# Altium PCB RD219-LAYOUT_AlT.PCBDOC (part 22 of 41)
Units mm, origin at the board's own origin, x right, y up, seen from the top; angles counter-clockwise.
Board outline 209.75 x 159.97 mm, 2 copper layers (TOP, BOTTOM), stack 0 mm thick; 398 components, 199 nets, 1469 pads, 0 vias.
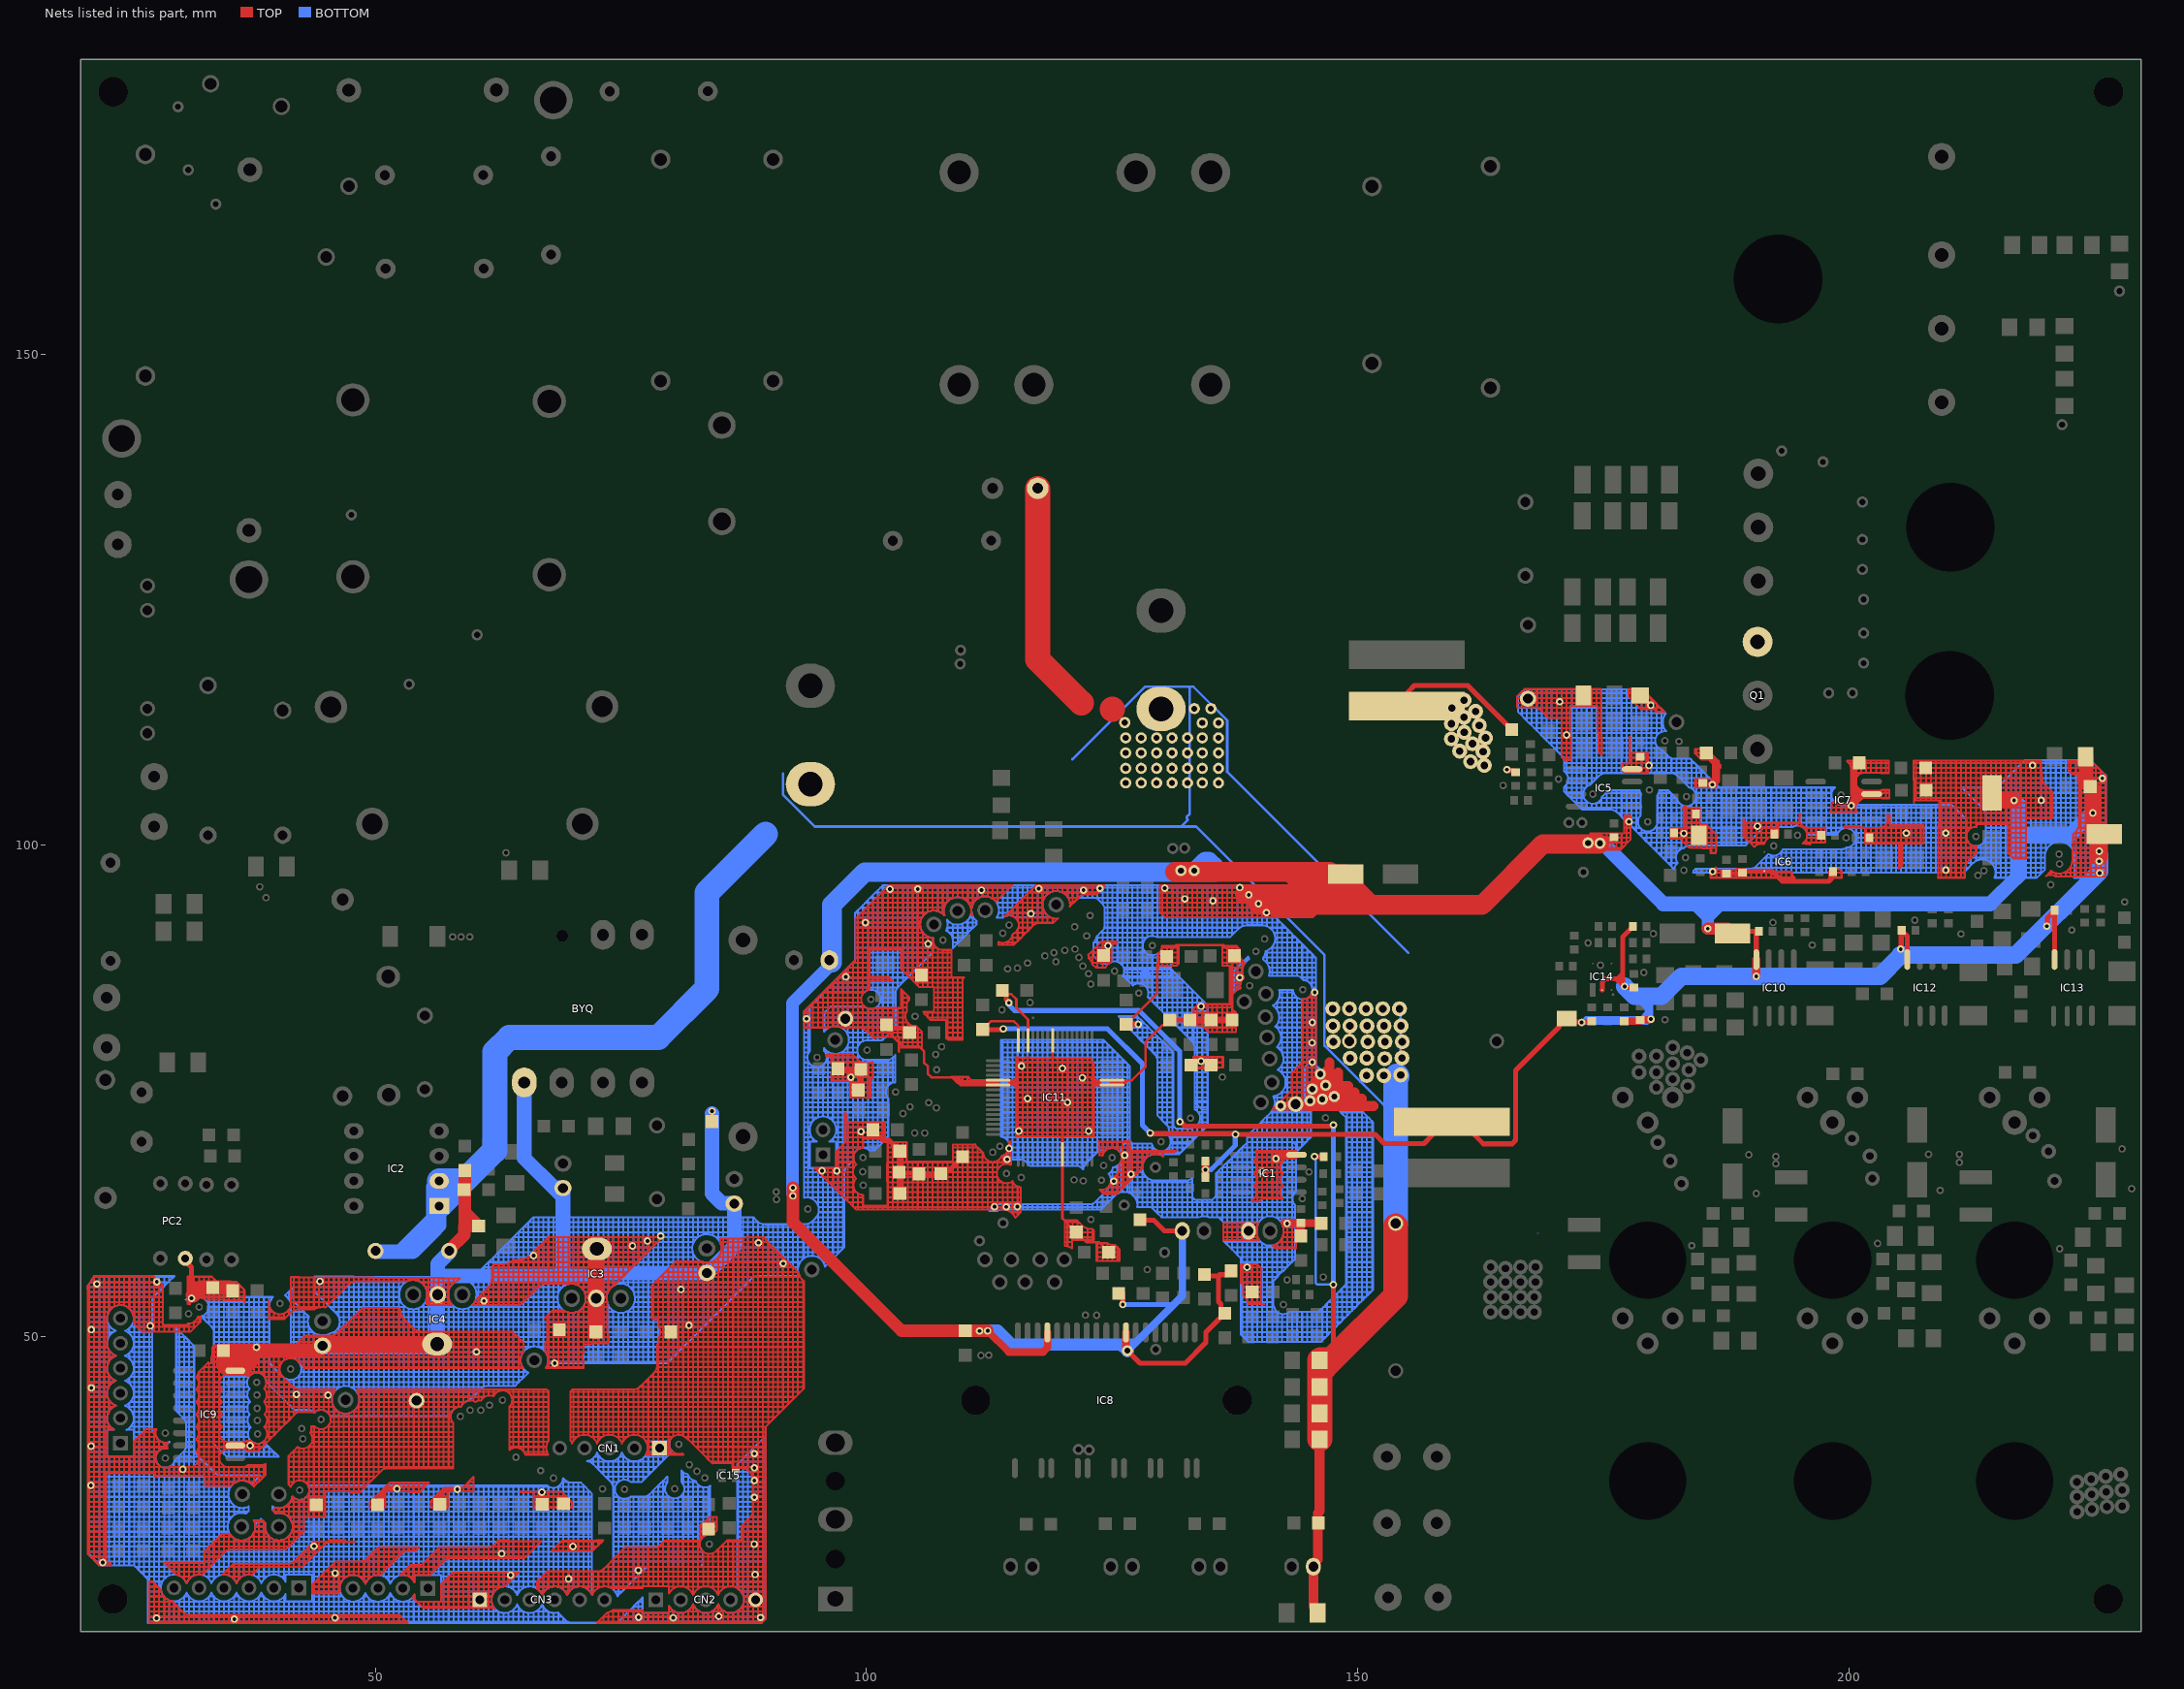
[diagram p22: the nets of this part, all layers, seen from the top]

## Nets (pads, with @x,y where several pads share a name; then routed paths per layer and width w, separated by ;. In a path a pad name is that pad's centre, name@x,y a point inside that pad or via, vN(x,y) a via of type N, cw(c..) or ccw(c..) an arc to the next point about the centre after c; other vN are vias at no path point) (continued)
GND: (continued)
  BOTTOM w0.203: 36.129,41.844 36.129,42.352 ; 36.129,41.844 36.637,41.844 ; 36.129,42.352 36.129,42.86 ; 36.129,42.352 36.637,42.352 ; 36.129,42.86 36.129,43.368 ; 36.129,42.86 36.637,42.86 ; 36.129,43.368 36.129,43.876 ; 36.129,43.368 36.637,43.368 ; 36.129,43.876 36.129,44.384 ; 36.129,43.876 36.637,43.876 ; 36.129,44.384 36.129,44.892 ; 36.129,44.384 36.637,44.384 ; 36.129,44.892 36.129,45.4 ; 36.129,44.892 36.637,44.892 ; 36.129,45.4 36.129,45.908 ; 36.129,45.4 36.637,45.4 ; 36.129,45.908 36.129,46.416 ; 36.129,45.908 36.637,45.908 ; 36.129,46.416 36.129,46.924 ; 36.129,46.416 36.637,46.416 ; 36.129,46.924 36.129,47.432 ; 36.129,46.924 36.637,46.924 ; 36.129,47.432 36.129,47.94 ; 36.129,47.432 36.637,47.432 ; 36.129,47.94 36.129,48.448 ; 36.129,47.94 36.637,47.94 ; 36.129,48.448 36.129,48.956 ; 36.129,48.448 36.637,48.448 ; 36.129,48.956 36.129,49.464 ; 36.129,48.956 36.637,48.956 ; 36.129,49.464 36.129,49.972 ; 36.129,49.464 36.637,49.464 ; 36.129,49.972 36.129,50.48 ; 36.129,49.972 36.637,49.972 ; 36.129,50.48 36.129,50.988 ; 36.129,50.48 36.637,50.48 ; 36.129,50.988 36.129,51.496 ; 36.129,50.988 36.637,50.988 ; 36.129,51.496 36.129,52.004 ; 36.129,51.496 36.637,51.496 ; 36.129,52.004 36.129,52.512 ; 36.129,52.004 36.637,52.004 ; 36.129,52.512 36.129,53.02 ; 36.129,52.512 36.637,52.512 ; 36.129,53.02 36.129,53.528 ; 36.129,53.02 36.637,53.02 ; 36.129,53.528 36.129,54.036 ; 36.129,53.528 36.637,53.528 ; 36.129,54.036 36.129,54.073 ; 36.129,54.036 36.637,54.036 ; 36.129,54.073 36.637,54.073 ; 36.424,25.588 cw(c37.145,24.445) 36.429,25.591 cw(c37.145,24.445) 36.637,25.697 ; 36.637,20.889 36.637,21.016 ; 36.637,20.889 37.145,20.889 ; 36.637,21.016 36.637,21.524 ; 36.637,21.016 37.145,21.016 ; 36.637,21.524 36.637,22.032 ; 36.637,21.524 37.145,21.524 ; 36.637,22.032 36.637,22.54 ; 36.637,22.032 37.145,22.032 ; 36.637,22.54 36.637,23.048 ; 36.637,22.54 37.145,22.54 ; 36.637,23.048 37.145,23.048 ; 36.637,23.048 36.637,23.193 ; 36.637,23.193 ccw(c37.145,24.445) 36.639,23.192 ccw(c37.145,24.445) 37.145,23.093 ; 36.637,25.697 cw(c37.145,24.445) 36.639,25.698 cw(c37.145,24.445) 37.145,25.797 ; 36.637,25.698 36.637,26.096 ; 36.637,26.096 36.637,26.604 ; 36.637,26.096 37.145,26.096 ; 36.637,26.604 36.637,27.112 ; 36.637,26.604 37.145,26.604 ; 36.637,27.112 36.637,27.62 ; 36.637,27.112 37.145,27.112 ; 36.637,27.62 36.637,28.128 ; 36.637,27.62 37.145,27.62 ; 36.637,28.128 36.637,28.636 ; 36.637,28.128 37.145,28.128 ; 36.637,28.636 36.637,29.144 ; 36.637,28.636 37.145,28.636 ; 36.637,29.144 37.145,29.144 ; 36.637,29.144 36.637,29.29 ; 36.637,29.29 ccw(c36.383,30.668) 36.793,29.328 ccw(c36.383,30.668) 37.145,29.492 ; 36.637,32.046 36.637,32.192 ; 36.637,32.192 37.044,32.192 ; 36.637,32.192 36.637,32.579 ; 36.637,32.579 ccw(c36.463,33.97) 37.115,32.729 ; 36.637,35.361 cw(c36.463,33.97) 37.056,35.24 ; 36.637,35.361 36.637,35.748 ; 36.637,35.748 36.637,35.908 ; 36.637,35.748 37.145,35.748 ; 36.637,35.908 37.145,35.908 ; 36.637,37.79 36.637,38.288 ; 36.637,37.79 37.145,37.79 ; 36.637,38.288 36.637,38.796 ; 36.637,38.288 37.145,38.288 ; 36.637,38.796 36.637,39.304 ; 36.637,38.796 pad.@37.145,38.796 ; 36.637,39.304 36.637,39.812 ; 36.637,39.304 37.145,39.304 ; 36.637,39.812 36.637,40.32 ; 36.637,39.812 37.087,39.812 ; 36.637,40.32 36.637,40.828 ; 36.637,40.32 37.064,40.32 ; 36.637,40.828 37.145,40.828 ; 36.637,40.828 36.637,41.336 ; 36.637,41.336 36.637,41.844 ; 36.637,41.844 36.637,42.352 ; 36.637,41.844 37.081,41.844 ; 36.637,42.352 36.637,42.86 ; 36.637,42.352 37.059,42.352 ; 36.637,42.86 36.637,43.368 ; 36.637,42.86 37.002,42.86 ; 36.637,43.368 37.145,43.368 ; 36.637,43.368 36.637,43.876 ; 36.637,43.876 36.637,44.384 ; 36.637,43.876 37.005,43.876 ; 36.637,44.384 36.637,44.892 ; 36.637,44.384 37.034,44.384 ; 36.637,44.892 36.637,45.4 ; 36.637,44.892 37.066,44.892 ; 36.637,45.4 36.637,45.908 ; 36.637,45.4 36.948,45.4 ; 36.637,45.908 36.637,46.416 ; 36.637,45.908 37.115,45.908 ; 36.637,46.416 36.637,46.924 ; 36.637,46.416 37.145,46.416 ; 36.637,46.924 36.637,47.432 ; 36.637,46.924 37.145,46.924 ; 36.637,47.432 36.637,47.94 ; 36.637,47.432 37.145,47.432 ; 36.637,47.94 36.637,48.448 ; 36.637,47.94 37.145,47.94 ; 36.637,48.448 36.637,48.956 ; 36.637,48.448 37.145,48.448 ; 36.637,48.956 36.637,49.464 ; 36.637,48.956 37.145,48.956 ; 36.637,49.464 36.637,49.972 ; 36.637,49.464 37.145,49.464 ; 36.637,49.972 36.637,50.48 ; 36.637,49.972 37.145,49.972 ; 36.637,50.48 36.637,50.988 ; 36.637,50.48 37.145,50.48 ; 36.637,50.988 36.637,51.496 ; 36.637,50.988 37.145,50.988 ; 36.637,51.496 36.637,52.004 ; 36.637,51.496 37.145,51.496 ; 36.637,52.004 36.637,52.512 ; 36.637,52.004 37.145,52.004 ; 36.637,52.512 36.637,53.02 ; 36.637,52.512 37.145,52.512 ; 36.637,53.02 36.637,53.528 ; 36.637,53.02 37.145,53.02 ; 36.637,53.528 36.637,54.036 ; 36.637,53.528 37.145,53.528 ; 36.637,54.036 36.637,54.073 ; 36.637,54.036 37.145,54.036 ; 36.637,54.073 37.145,54.073 ; 36.948,45.4 ccw(c37.93,45.359) 36.948,45.394 ccw(c37.93,45.359) 37.066,44.892 ; 36.948,45.4 cw(c37.93,45.359) 37.115,45.908 ; 37.002,42.86 ccw(c37.973,42.712) 37.059,42.352 ; 37.002,42.86 cw(c37.973,42.712) 37.003,42.866 cw(c37.973,42.712) 37.145,43.241 ; 37.005,43.876 ccw(c37.967,44.076) 37.006,43.872 ccw(c37.967,44.076) 37.145,43.537 ; 37.005,43.876 cw(c37.967,44.076) 37.032,44.379 cw(c37.967,44.076) 37.034,44.384 ; 37.034,44.384 cw(c37.967,44.076) 37.145,44.615 ; 37.044,32.192 37.115,32.263 37.115,32.729 ; 37.056,35.24 cw(c36.463,33.97) 37.143,35.196 cw(c36.463,33.97) 37.145,35.194 ; 37.056,35.24 37.145,35.24 ; 37.059,42.352 ccw(c37.973,42.712) 37.145,42.183 ; 37.064,40.32 ccw(c38.024,40.11) 37.062,40.314 ccw(c38.024,40.11) 37.087,39.812 ; 37.064,40.32 cw(c38.024,40.11) 37.145,40.55 ; 37.066,44.892 ccw(c37.93,45.359) 37.145,44.769 ; 37.081,41.844 cw(c37.995,41.485) 37.145,41.978 ; 37.087,39.812 ccw(c38.024,40.11) 37.145,39.67 ; 37.115,45.908 cw(c37.93,45.359) 37.145,45.95 37.145,46.416 ; 37.145,20.889 37.145,21.016 ; 37.145,20.889 37.653,20.889 ; 37.145,21.016 37.145,21.524 ; 37.145,21.016 37.653,21.016 ; 37.145,21.524 37.145,22.032 ; 37.145,21.524 37.653,21.524 ; 37.145,22.032 37.145,22.54 ; 37.145,22.032 37.653,22.032 ; 37.145,22.54 37.145,23.048 ; 37.145,22.54 37.653,22.54 ; 37.145,23.048 37.653,23.048 ; 37.145,23.048 37.145,23.093 ; 37.145,23.093 ccw(c37.145,24.445) 37.651,23.192 ccw(c37.145,24.445) 37.653,23.192 ; 37.145,25.797 cw(c37.145,24.445) 37.651,25.698 cw(c37.145,24.445) 37.653,25.698 ; 37.145,25.797 37.145,26.096 ; 37.145,26.096 37.145,26.604 ; 37.145,26.096 37.653,26.096 ; 37.145,26.604 37.145,27.112 ; 37.145,26.604 37.653,26.604 ; 37.145,27.112 37.145,27.62 ; 37.145,27.112 37.653,27.112 ; 37.145,27.62 37.145,28.128 ; 37.145,27.62 37.653,27.62 ; 37.145,28.128 37.145,28.636 ; 37.145,28.128 37.653,28.128 ; 37.145,28.636 37.145,29.144 ; 37.145,28.636 37.653,28.636 ; 37.145,29.144 37.653,29.144 ; 37.145,29.144 37.145,29.492 ; 37.145,29.492 ccw(c36.383,30.668) 37.146,29.493 ccw(c36.383,30.668) 37.349,29.652 ; 37.145,35.194 37.145,35.24 ; 37.145,35.24 37.145,35.748 ; 37.145,35.24 37.639,35.24 ; 37.145,35.748 37.145,35.908 ; 37.145,35.748 37.653,35.748 ; 37.145,35.908 37.653,35.908 ; 37.145,37.79 37.145,38.288 ; 37.145,37.79 37.653,37.79 ; 37.145,38.288 pad.@37.145,38.796 ; 37.145,38.288 37.653,38.288 ; pad.@37.145,38.796 37.653,38.796 ; pad.@37.145,38.796 37.145,39.304 ; 37.145,39.304 37.461,39.304 ; 37.145,39.304 37.145,39.67 ; 37.145,39.67 ccw(c38.024,40.11) 37.148,39.664 ccw(c38.024,40.11) 37.46,39.305 ccw(c38.024,40.11) 37.461,39.304 ; 37.145,40.55 37.145,40.828 ; 37.145,40.828 37.145,40.992 ; 37.145,40.828 37.264,40.828 ; 37.145,40.992 ccw(c37.995,41.485) 37.264,40.828 ; 37.145,41.978 37.145,42.183 ; 37.145,43.241 cw(c37.973,42.712) 37.241,43.368 ; 37.145,43.241 37.145,43.368 ; 37.145,43.368 37.241,43.368 ; 37.145,43.368 37.145,43.537 ; 37.145,44.615 37.145,44.769 ; 37.145,46.416 37.145,46.924 ; 37.145,46.416 37.653,46.416 ; 37.145,46.924 37.145,47.432 ; 37.145,46.924 37.653,46.924 ; 37.145,47.432 37.145,47.94 ; 37.145,47.432 37.653,47.432 ; 37.145,47.94 37.145,48.448 ; 37.145,47.94 37.653,47.94 ; 37.145,48.448 37.145,48.956 ; 37.145,48.448 37.653,48.448 ; 37.145,48.956 37.145,49.464 ; 37.145,48.956 pad.@37.653,48.956 ; 37.145,49.464 37.145,49.972 ; 37.145,49.464 37.653,49.464 ; 37.145,49.972 37.145,50.48 ; 37.145,49.972 37.653,49.972 ; 37.145,50.48 37.145,50.988 ; 37.145,50.48 37.653,50.48 ; 37.145,50.988 37.145,51.496 ; 37.145,50.988 37.653,50.988 ; 37.145,51.496 37.145,52.004 ; 37.145,51.496 37.653,51.496 ; 37.145,52.004 37.145,52.512 ; 37.145,52.004 37.653,52.004 ; 37.145,52.512 37.145,53.02 ; 37.145,52.512 37.653,52.512 ; 37.145,53.02 37.145,53.528 ; 37.145,53.02 37.653,53.02 ; 37.145,53.528 37.145,54.036 ; 37.145,53.528 37.653,53.528 ; 37.145,54.036 37.145,54.073 ; 37.145,54.036 37.653,54.036 ; 37.145,54.073 37.653,54.073 ; 37.349,29.652 ccw(c36.383,30.668) 37.357,29.66 ccw(c36.383,30.668) 37.653,30.075 37.653,29.652 ; 37.349,29.652 37.653,29.652 ; 37.461,39.304 ccw(c38.024,40.11) 37.653,39.2 ; 37.639,35.24 37.653,35.254 ; 37.653,20.889 37.653,21.016 ; 37.653,20.889 38.161,20.889 ; 37.653,21.016 37.653,21.524 ; 37.653,21.016 38.161,21.016 ; 37.653,21.524 37.653,22.032 ; 37.653,21.524 38.161,21.524 ; 37.653,22.032 37.653,22.54 ; 37.653,22.032 38.161,22.032 ; 37.653,22.54 37.653,23.048 ; 37.653,22.54 38.161,22.54 ; 37.653,23.048 38.161,23.048 ; 37.653,23.048 37.653,23.192 ; 37.653,23.192 ccw(c37.145,24.445) 38.161,23.554 ; 37.653,25.698 37.653,26.096 ; 37.653,26.096 37.653,26.604 ; 37.653,26.096 38.161,26.096 ; 37.653,26.604 37.653,27.112 ; 37.653,26.604 38.161,26.604 ; 37.653,27.112 37.653,27.62 ; 37.653,27.112 38.161,27.112 ; 37.653,27.62 37.653,28.128 ; 37.653,27.62 38.161,27.62 ; 37.653,28.128 37.653,28.636 ; 37.653,28.128 38.161,28.128 ; 37.653,28.636 37.653,29.144 ; 37.653,28.636 38.161,28.636 ; 37.653,29.144 37.653,29.652 ; 37.653,29.144 38.161,29.144 ; 37.653,29.652 38.161,29.652 ; 37.653,35.254 38.161,35.762 ; 37.653,35.254 37.653,35.748 ; 37.653,35.748 37.653,35.908 ; 37.653,35.908 38.161,35.908 ; 37.653,37.79 37.653,38.288 ; 37.653,37.79 38.161,37.79 ; 37.653,38.288 37.653,38.796 ; 37.653,38.288 38.161,38.288 ; 37.653,38.796 38.161,38.796 ; 37.653,38.796 37.653,39.2 ; 37.653,46.302 cw(c37.93,45.359) 37.659,46.304 cw(c37.93,45.359) 37.93,46.342 cw(c37.93,45.359) 38.161,46.314 ; 37.653,46.302 37.653,46.416 ; 37.653,46.416 37.653,46.924 ; 37.653,46.416 38.161,46.416 ; 37.653,46.924 37.653,47.432 ; 37.653,46.924 38.161,46.924 ; 37.653,47.432 37.653,47.94 ; 37.653,47.432 38.161,47.432 ; 37.653,47.94 37.653,48.448 ; 37.653,47.94 38.161,47.94 ; 37.653,48.448 38.161,48.448 ; 37.653,48.448 pad.@37.653,48.956 ; pad.@37.653,48.956 37.653,49.464 ; pad.@37.653,48.956 pad.@38.161,48.956 ; 37.653,49.464 37.653,49.972 ; 37.653,49.464 38.161,49.464 ; 37.653,49.972 37.653,50.48 ; 37.653,49.972 38.161,49.972 ; 37.653,50.48 37.653,50.988 ; 37.653,50.48 38.161,50.48 ; 37.653,50.988 37.653,51.496 ; 37.653,50.988 38.161,50.988 ; 37.653,51.496 37.653,52.004 ; 37.653,51.496 38.161,51.496 ; 37.653,52.004 37.653,52.512 ; 37.653,52.004 38.161,52.004 ; 37.653,52.512 37.653,53.02 ; 37.653,52.512 38.161,52.512 ; 37.653,53.02 37.653,53.528 ; 37.653,53.02 38.161,53.02 ; 37.653,53.528 37.653,54.036 ; 37.653,53.528 38.161,53.528 ; 37.653,54.036 37.653,54.073 ; 37.653,54.036 38.161,54.036 ; 37.653,54.073 38.161,54.073 ; 37.689,30.16 ccw(c36.383,30.668) 37.785,30.668 ; 37.689,30.16 38.161,30.16 ; 37.772,30.859 cw(c36.383,30.668) 37.785,30.668 ; 37.772,30.859 38.088,31.176 ; 37.785,30.668 38.161,30.668 ; 38.088,31.176 38.161,31.176 ; 38.088,31.176 38.161,31.249 ; 38.161,20.889 38.161,21.016 ; 38.161,20.889 38.669,20.889 ; 38.161,21.016 38.161,21.524 ; 38.161,21.016 38.669,21.016 ; 38.161,21.524 38.161,22.032 ; 38.161,21.524 38.669,21.524 ; 38.161,22.032 38.161,22.54 ; 38.161,22.032 38.669,22.032 ; 38.161,22.54 38.161,23.048 ; 38.161,22.54 38.669,22.54 ; 38.161,23.048 38.669,23.048 ; 38.161,23.048 38.161,23.554 ; 38.161,23.554 ccw(c37.145,24.445) 38.163,23.556 ; 38.161,25.336 cw(c37.145,24.445) 38.165,25.332 cw(c37.145,24.445) 38.338,25.08 ; 38.161,25.336 38.161,25.588 ; 38.161,25.588 38.161,26.096 ; 38.161,25.588 38.669,25.588 ; 38.161,26.096 38.161,26.604 ; 38.161,26.096 38.669,26.096 ; 38.161,26.604 38.161,27.112 ; 38.161,26.604 38.669,26.604 ; 38.161,27.112 38.161,27.62 ; 38.161,27.112 38.669,27.112 ; 38.161,27.62 38.161,28.128 ; 38.161,27.62 38.669,27.62 ; 38.161,28.128 38.161,28.636 ; 38.161,28.128 38.669,28.128 ; 38.161,28.636 38.161,29.144 ; 38.161,28.636 38.669,28.636 ; 38.161,29.144 38.161,29.652 ; 38.161,29.144 38.669,29.144 ; 38.161,29.652 38.161,30.16 ; 38.161,29.652 38.669,29.652 ; 38.161,30.16 38.161,30.668 ; 38.161,30.16 38.669,30.16 ; 38.161,30.668 38.161,31.176 ; 38.161,30.668 38.669,30.668 ; 38.161,31.176 38.655,31.176 ; 38.161,31.176 38.161,31.249 ; 38.161,35.762 38.307,35.908 38.161,35.908 ; 38.161,35.762 38.161,35.908 ; 38.161,37.79 38.669,37.79 ; 38.161,37.79 38.161,38.288 ; 38.161,38.288 38.161,38.796 ; 38.161,38.288 38.669,38.288 ; 38.161,38.796 38.669,38.796 ; 38.161,38.796 38.161,39.137 ccw(c38.024,40.11) 38.625,39.333 ; 38.161,46.314 cw(c37.93,45.359) 38.669,46.007 ; 38.161,46.314 38.161,46.416 ; 38.161,46.416 38.161,46.924 ; 38.161,46.416 38.669,46.416 ; 38.161,46.924 38.669,46.924 ; 38.161,46.924 38.161,47.432 ; 38.161,47.432 38.161,47.94 ; 38.161,47.432 38.669,47.432 ; 38.161,47.94 38.669,47.94 ; 38.161,47.94 38.161,48.448 ; 38.161,48.448 38.669,48.448 ; 38.161,48.448 pad.@38.161,48.956 ; pad.@38.161,48.956 38.161,49.464 ; pad.@38.161,48.956 38.669,48.956 ; 38.161,49.464 38.161,49.972 ; 38.161,49.464 38.669,49.464 ; 38.161,49.972 38.161,50.48 ; 38.161,49.972 38.669,49.972 ; 38.161,50.48 38.669,50.48 ; 38.161,50.48 38.161,50.988 ; 38.161,50.988 38.669,50.988 ; 38.161,50.988 38.161,51.496 ; 38.161,51.496 38.161,52.004 ; 38.161,51.496 38.669,51.496 ; 38.161,52.004 38.669,52.004 ; 38.161,52.004 38.161,52.512 ; 38.161,52.512 38.161,53.02 ; 38.161,52.512 38.669,52.512 ; 38.161,53.02 38.669,53.02 ; 38.161,53.02 38.161,53.528 ; 38.161,53.528 38.669,53.528 ; 38.161,53.528 38.161,54.036 ; 38.161,54.036 38.669,54.036 ; 38.161,54.036 38.161,54.073 ; 38.161,54.073 38.669,54.073 ; 38.163,23.556 ccw(c37.145,24.445) 38.165,23.558 ccw(c37.145,24.445) 38.415,23.982 ccw(c39.685,24.445) 38.665,23.558 ccw(c39.685,24.445) 38.667,23.556 ; 38.163,23.556 38.667,23.556 ; 38.338,25.08 cw(c37.145,24.445) 38.415,24.908 cw(c39.685,24.445) 38.492,25.08 ; 38.338,25.08 38.492,25.08 ; 38.625,39.333 38.669,39.29 ; 38.655,31.176 38.669,31.162 ; 38.667,23.556 ccw(c39.685,24.445) 38.669,23.554 ; 38.669,20.889 38.669,21.016 ; 38.669,20.889 39.177,20.889 ; 38.669,21.016 38.669,21.524 ; 38.669,21.016 39.177,21.016 ; 38.669,21.524 38.669,22.032 ; 38.669,21.524 39.177,21.524 ; 38.669,22.032 38.669,22.54 ; 38.669,22.032 39.177,22.032 ; 38.669,22.54 38.669,23.048 ; 38.669,22.54 39.177,22.54 ; 38.669,23.048 39.177,23.048 ; 38.669,23.048 38.669,23.554 ; 38.669,23.554 ccw(c39.685,24.445) 39.177,23.193 ; 38.669,25.588 38.669,26.096 ; 38.669,25.588 38.964,25.588 ; 38.669,26.096 38.669,26.604 ; 38.669,26.096 39.177,26.096 ; 38.669,26.604 38.669,27.112 ; 38.669,26.604 39.177,26.604 ; 38.669,27.112 38.669,27.62 ; 38.669,27.112 39.177,27.112 ; 38.669,27.62 38.669,28.128 ; 38.669,27.62 39.177,27.62 ; 38.669,28.128 38.669,28.636 ; 38.669,28.128 39.177,28.128 ; 38.669,28.636 38.669,29.144 ; 38.669,28.636 39.177,28.636 ; 38.669,29.144 38.669,29.652 ; 38.669,29.144 39.177,29.144 ; 38.669,29.652 39.177,29.652 ; 38.669,29.652 38.669,30.16 ; 38.669,30.16 38.669,30.668 ; 38.669,30.16 38.887,30.16 ; 38.669,30.668 38.669,31.162 ; 38.669,30.668 38.791,30.668 ; 38.669,31.162 38.831,30.999 ; 38.669,37.79 39.177,37.79 ; 38.669,37.79 38.669,38.288 ; 38.669,38.288 38.669,38.796 ; 38.669,38.288 39.177,38.288 ; 38.669,38.796 38.669,39.29 ; 38.669,38.796 39.163,38.796 ; 38.669,39.29 39.163,38.796 ; 38.669,46.007 cw(c37.93,45.359) 38.745,45.908 ; 38.669,46.007 38.669,46.416 ; 38.669,46.416 38.669,46.924 ; 38.669,46.416 39.177,46.416 ; 38.669,46.924 38.669,47.432 ; 38.669,46.924 39.177,46.924 ; 38.669,47.432 38.669,47.94 ; 38.669,47.432 39.177,47.432 ; 38.669,47.94 38.669,48.448 ; 38.669,47.94 39.177,47.94 ; 38.669,48.448 38.669,48.956 ; 38.669,48.448 39.177,48.448 ; 38.669,48.956 38.669,49.464 ; 38.669,48.956 39.177,48.956 ; 38.669,49.464 38.669,49.972 ; 38.669,49.464 39.177,49.464 ; 38.669,49.972 38.669,50.48 ; 38.669,49.972 39.177,49.972 ; 38.669,50.48 38.669,50.988 ; 38.669,50.48 39.177,50.48 ; 38.669,50.988 38.669,51.496 ; 38.669,50.988 39.177,50.988 ; 38.669,51.496 38.669,52.004 ; 38.669,51.496 39.177,51.496 ; 38.669,52.004 39.177,52.004 ; 38.669,52.004 38.669,52.512 ; 38.669,52.512 38.669,53.02 ; 38.669,52.512 39.177,52.512 ; 38.669,53.02 38.669,53.528 ; 38.669,53.02 39.177,53.02 ; 38.669,53.528 38.669,54.036 ; 38.669,53.528 39.177,53.528 ; 38.669,54.036 38.669,54.073 ; 38.669,54.036 39.177,54.036 ; 38.669,54.073 39.177,54.073 ; 38.745,45.908 39.177,45.908 ; 38.791,30.668 ccw(c40.193,30.668) 38.887,30.16 ; 38.964,25.588 cw(c39.685,24.445) 38.969,25.591 cw(c39.685,24.445) 39.177,25.697 ; 39.163,38.796 39.177,38.782 ; 39.177,20.889 39.177,21.016 ; 39.177,20.889 39.685,20.889 ; 39.177,21.016 39.177,21.524 ; 39.177,21.016 39.685,21.016 ; 39.177,21.524 39.177,22.032 ; 39.177,21.524 39.685,21.524 ; 39.177,22.032 39.177,22.54 ; 39.177,22.032 39.685,22.032 ; 39.177,22.54 39.177,23.048 ; 39.177,22.54 39.685,22.54 ; 39.177,23.048 39.685,23.048 ; 39.177,23.048 39.177,23.193 ; 39.177,23.193 ccw(c39.685,24.445) 39.179,23.192 ccw(c39.685,24.445) 39.685,23.093 ; 39.177,25.697 cw(c39.685,24.445) 39.179,25.698 cw(c39.685,24.445) 39.685,25.797 ; 39.177,25.698 39.177,26.096 ; 39.177,26.096 39.177,26.604 ; 39.177,26.096 39.685,26.096 ; 39.177,26.604 39.177,27.112 ; 39.177,26.604 39.685,26.604 ; 39.177,27.112 39.177,27.62 ; 39.177,27.112 39.685,27.112 ; 39.177,27.62 39.177,28.128 ; 39.177,27.62 39.685,27.62 ; 39.177,28.128 39.177,28.636 ; 39.177,28.128 39.685,28.128 ; 39.177,28.636 39.177,29.144 ; 39.177,28.636 39.685,28.636 ; 39.177,29.144 39.177,29.652 ; 39.177,29.144 39.685,29.144 ; 39.177,29.652 39.227,29.652 ; 39.177,37.79 39.177,38.288 ; 39.177,37.79 39.685,37.79 ; 39.177,38.288 39.177,38.782 ; 39.177,38.288 39.671,38.288 ; 39.177,38.782 39.671,38.288 ; 39.177,45.143 39.177,45.4 ; 39.177,45.143 39.428,44.892 ; 39.177,45.4 39.685,45.4 ; 39.177,45.4 39.177,45.908 ; 39.177,45.908 39.685,45.908 ; 39.177,45.908 39.177,46.416 ; 39.177,46.416 39.177,46.924 ; 39.177,46.416 39.685,46.416 ; 39.177,46.924 39.177,47.432 ; 39.177,46.924 39.608,46.924 ; 39.177,47.432 39.177,47.94 ; 39.177,47.432 39.272,47.432 ; 39.177,47.94 39.177,48.448 ; 39.177,47.94 39.218,47.94 ; 39.177,48.448 39.177,48.956 ; 39.177,48.448 39.218,48.448 ; 39.177,48.956 39.177,49.464 ; 39.177,48.956 39.218,48.956 ; 39.177,49.464 39.177,49.972 ; 39.177,49.464 39.218,49.464 ; 39.177,49.972 39.177,50.48 ; 39.177,49.972 39.218,49.972 ; 39.177,50.48 39.177,50.988 ; 39.177,50.48 39.218,50.48 ; 39.177,50.988 39.177,51.496 ; 39.177,50.988 39.218,50.988 ; 39.177,51.496 39.177,52.004 ; 39.177,51.496 39.218,51.496 ; 39.177,52.004 39.177,52.512 ; 39.177,52.004 39.218,52.004 ; 39.177,52.512 39.177,53.02 ; 39.177,52.512 39.218,52.512 ; 39.177,53.02 39.177,53.528 ; 39.177,53.02 39.218,53.02 ; 39.177,53.528 39.177,54.036 ; 39.177,53.528 39.286,53.528 ; 39.177,54.036 39.177,54.073 ; 39.177,54.036 39.559,54.036 ; 39.218,47.77 ccw(c40.32,47.77) 39.272,47.432 ; 39.218,47.77 ccw(c40.32,47.77) 39.272,47.432 ; 39.218,47.77 39.218,47.94 ; 39.218,47.94 39.218,48.448 ; 39.218,48.448 39.218,48.956 ; 39.218,48.956 39.218,49.464 ; 39.218,49.464 39.218,49.972 ; 39.218,49.972 39.218,50.48 ; 39.218,50.48 39.218,50.988 ; 39.218,50.988 39.218,51.496 ; 39.218,51.496 39.218,52.004 ; 39.218,52.004 39.218,52.512 ; 39.218,52.512 39.218,53.02 ; 39.218,53.02 39.218,53.147 cw(c40.32,53.147) 39.286,53.528 ; 39.227,29.652 ccw(c40.193,30.668) 39.685,29.362 ; 39.272,47.43 ccw(c40.32,47.77) 39.541,46.991 cw(c40.32,47.77) 39.272,47.43 ; 39.272,47.43 cw(c40.32,47.77) 39.272,47.432 ; 39.272,47.43 cw(c40.32,47.77) 39.272,47.432 ; 39.362,53.692 cw(c40.296,53.386) 39.559,54.036 ; 39.428,44.892 39.685,44.635 ; 39.428,44.892 39.685,44.892 ; 39.608,46.924 39.685,46.847 ; 39.671,38.288 39.685,38.274 ; 39.685,20.889 39.685,21.016 ; 39.685,20.889 40.193,20.889 ; 39.685,21.016 39.685,21.524 ; 39.685,21.016 40.193,21.016 ; 39.685,21.524 39.685,22.032 ; 39.685,21.524 40.193,21.524 ; 39.685,22.032 39.685,22.54 ; 39.685,22.032 40.193,22.032 ; 39.685,22.54 39.685,23.048 ; 39.685,22.54 40.193,22.54 ; 39.685,23.048 40.193,23.048 ; 39.685,23.048 39.685,23.093 ; 39.685,23.093 ccw(c39.685,24.445) 40.191,23.192 ccw(c39.685,24.445) 40.193,23.192 ; 39.685,25.797 cw(c39.685,24.445) 40.191,25.698 cw(c39.685,24.445) 40.193,25.698 ; 39.685,25.797 39.685,26.096 ; 39.685,26.096 39.685,26.604 ; 39.685,26.096 40.193,26.096 ; 39.685,26.604 39.685,27.112 ; 39.685,26.604 40.193,26.604 ; 39.685,27.112 39.685,27.62 ; 39.685,27.112 40.193,27.112 ; 39.685,27.62 39.685,28.128 ; 39.685,27.62 40.193,27.62 ; 39.685,28.128 39.685,28.636 ; 39.685,28.128 40.193,28.128 ; 39.685,28.636 39.685,29.144 ; 39.685,28.636 40.193,28.636 ; 39.685,29.144 40.193,29.144 ; 39.685,29.144 39.685,29.362 ; 39.685,29.362 ccw(c40.193,30.668) 39.691,29.359 ccw(c40.193,30.668) 40.193,29.266 ; 39.685,32.206 39.699,32.192 ; 39.685,32.206 39.685,32.664 ; 39.685,32.664 ccw(c40.193,33.97) 40.193,32.568 ; 39.685,37.79 40.169,37.79 39.685,38.274 ; 39.685,37.79 39.685,38.274 ; 39.685,44.635 39.936,44.384 ; 39.685,44.635 39.685,44.892 ; 39.685,44.892 39.685,45.4 ; 39.685,44.892 40.193,44.892 ; 39.685,45.4 40.193,45.4 ; 39.685,45.4 39.685,45.908 ; 39.685,45.908 40.193,45.908 ; 39.685,45.908 39.685,46.416 ; 39.685,46.416 39.685,46.847 ; 39.685,46.416 40.116,46.416 ; 39.685,46.847 40.116,46.416 ; 39.699,32.192 40.193,32.192 ; 39.699,32.192 39.862,32.03 ; 39.862,32.03 cw(c40.193,30.668) 40.193,32.07 ; 39.936,44.384 40.193,44.384 ; 39.936,44.384 40.193,44.127 ; 40.116,46.416 40.193,46.339 ; 40.193,20.889 40.193,21.016 ; 40.193,20.889 40.701,20.889 ; 40.193,21.016 40.193,21.524 ; 40.193,21.016 40.701,21.016 ; 40.193,21.524 40.193,22.032 ; 40.193,21.524 40.701,21.524 ; 40.193,22.032 40.193,22.54 ; 40.193,22.032 40.701,22.032 ; 40.193,22.54 40.193,23.048 ; 40.193,22.54 40.701,22.54 ; 40.193,23.048 40.701,23.048 ; 40.193,23.048 40.193,23.192 ; 40.193,23.192 ccw(c39.685,24.445) 40.701,23.554 ; 40.193,25.698 40.193,26.096 ; 40.193,26.096 40.193,26.604 ; 40.193,26.096 40.701,26.096 ; 40.193,26.604 40.193,27.112 ; 40.193,26.604 40.701,26.604 ; 40.193,27.112 40.193,27.62 ; 40.193,27.112 40.701,27.112 ; 40.193,27.62 40.193,28.128 ; 40.193,27.62 40.701,27.62 ; 40.193,28.128 40.193,28.636 ; 40.193,28.128 40.701,28.128 ; 40.193,28.636 40.193,29.144 ; 40.193,28.636 40.701,28.636 ; 40.193,29.144 40.701,29.144 ; 40.193,29.144 40.193,29.266 ; 40.193,29.266 ccw(c40.193,30.668) 40.695,29.359 ccw(c40.193,30.668) 40.701,29.362 ; 40.193,32.07 cw(c40.193,30.668) 40.695,31.977 cw(c40.193,30.668) 40.701,31.974 ; 40.193,32.07 40.193,32.192 ; 40.193,32.192 40.701,32.192 ; 40.193,32.192 40.193,32.568 ; 40.193,32.568 ccw(c40.193,33.97) 40.701,32.664 ; 40.193,44.127 40.193,44.384 ; 40.193,44.127 40.444,43.876 ; 40.193,44.384 40.193,44.892 ; 40.193,44.384 40.701,44.384 ; 40.193,44.892 40.193,45.4 ; 40.193,44.892 40.701,44.892 ; 40.193,45.4 40.701,45.4 ; 40.193,45.4 40.193,45.908 ; 40.193,45.908 40.193,46.339 ; 40.193,45.908 40.625,45.908 ; 40.193,46.339 40.597,45.935 ccw(c41.376,46.714) 40.625,45.908 ; 40.444,43.876 40.701,43.619 ; 40.444,43.876 40.701,43.876 ; 40.625,45.908 ccw(c41.376,46.714) 40.701,45.844 ; 40.701,20.889 40.701,21.016 ; 40.701,20.889 41.209,20.889 ; 40.701,21.016 40.701,21.524 ; 40.701,21.016 41.209,21.016 ; 40.701,21.524 40.701,22.032 ; 40.701,21.524 41.209,21.524 ; 40.701,22.032 40.701,22.54 ; 40.701,22.032 41.209,22.032 ; 40.701,22.54 40.701,23.048 ; 40.701,22.54 41.209,22.54 ; 40.701,23.048 41.209,23.048 ; 40.701,23.048 40.701,23.554 ; 40.701,23.554 ccw(c39.685,24.445) 40.703,23.556 ; 40.701,25.336 cw(c39.685,24.445) 40.705,25.332 cw(c39.685,24.445) 40.873,25.089 ; 40.701,25.336 40.701,25.588 ; 40.701,25.588 40.701,26.096 ; 40.701,25.588 40.873,25.588 ; 40.701,26.096 40.701,26.604 ; 40.701,26.096 41.209,26.096 ; 40.701,26.604 40.701,27.112 ; 40.701,26.604 41.209,26.604 ; 40.701,27.112 40.701,27.62 ; 40.701,27.112 41.209,27.112 ; 40.701,27.62 40.701,28.128 ; 40.701,27.62 41.209,27.62 ; 40.701,28.128 40.701,28.636 ; 40.701,28.128 41.209,28.128 ; 40.701,28.636 40.701,29.144 ; 40.701,28.636 41.209,28.636 ; 40.701,29.144 41.209,29.144 ; 40.701,29.144 40.701,29.362 ; 40.701,29.362 ccw(c40.193,30.668) 41.159,29.652 ; 40.701,31.974 cw(c40.193,30.668) 41.159,31.684 ; 40.701,31.974 40.701,32.192 ; 40.701,32.192 41.209,32.192 ; 40.701,32.192 40.701,32.664 ; 40.701,43.619 40.952,43.368 ; 40.701,43.619 40.701,43.876 ; 40.701,43.876 40.701,44.384 ; 40.701,43.876 41.209,43.876 ; 40.701,44.384 40.701,44.892 ; 40.701,44.384 41.209,44.384 ; 40.701,44.892 40.701,45.4 ; 40.701,44.892 41.209,44.892 ; 40.701,45.4 41.209,45.4 ; 40.701,45.4 40.701,45.844 ; 40.701,45.844 ccw(c41.376,46.714) 41.204,45.626 ccw(c41.376,46.714) 41.209,45.625 ; 40.703,23.556 ccw(c39.685,24.445) 40.705,23.558 ccw(c39.685,24.445) 40.873,23.801 ; 40.703,23.556 40.873,23.556 ; 40.873,23.556 40.873,23.093 41.209,23.093 ; 40.873,23.556 40.873,23.801 ; 40.873,25.089 40.873,25.588 ; 40.873,25.588 40.873,25.797 41.209,25.797 ; 40.952,43.368 41.209,43.368 ; 40.952,43.368 41.209,43.111 ; 41.034,54.036 cw(c40.296,53.386) 41.153,53.868 ; 41.034,54.036 41.209,54.036 ; 41.143,54.544 41.209,54.544 ; 41.143,54.544 41.631,55.032 41.631,54.544 ; 41.153,53.868 cw(c40.32,53.147) 41.209,53.798 ; 41.159,29.652 ccw(c40.193,30.668) 41.201,29.694 ccw(c40.193,30.668) 41.209,29.702 ; 41.159,29.652 41.209,29.652 ; 41.159,31.684 41.209,31.684 ; 41.209,20.889 41.209,21.016 ; 41.209,20.889 41.717,20.889 ; 41.209,21.016 41.209,21.524 ; 41.209,21.016 41.717,21.016 ; 41.209,21.524 41.209,22.032 ; 41.209,21.524 41.717,21.524 ; 41.209,22.032 41.209,22.54 ; 41.209,22.032 41.717,22.032 ; 41.209,22.54 41.209,23.048 ; 41.209,22.54 41.717,22.54 ; 41.209,23.048 41.209,23.093 ; 41.209,23.048 41.717,23.048 ; 41.209,23.093 41.717,23.093 ; 41.209,25.797 41.209,26.096 ; 41.209,25.797 41.717,25.797 ; 41.209,26.096 41.209,26.604 ; 41.209,26.096 41.717,26.096 ; 41.209,26.604 41.717,26.604 ; 41.209,26.604 41.209,27.112 ; 41.209,27.112 41.209,27.62 ; 41.209,27.112 41.717,27.112 ; 41.209,27.62 41.209,28.128 ; 41.209,27.62 41.717,27.62 ; 41.209,28.128 41.209,28.636 ; 41.209,28.128 41.717,28.128 ; 41.209,28.636 41.209,29.144 ; 41.209,28.636 41.717,28.636 ; 41.209,29.144 41.209,29.652 ; 41.209,29.144 41.717,29.144 ; 41.209,29.652 41.717,29.652 ; 41.209,29.652 41.209,29.702 ; 41.209,31.684 41.717,31.684 ; 41.209,31.684 41.209,32.192 ; 41.209,32.192 41.717,32.192 ; 41.209,32.192 41.209,32.7 ; 41.209,32.7 41.717,32.7 ; 41.209,32.7 40.786,32.7 ccw(c40.193,33.97) 41.201,32.996 ccw(c40.193,33.97) 41.209,33.004 ; 41.209,32.7 41.209,33.004 ; 41.209,33.004 ccw(c40.193,33.97) 41.368,33.207 ccw(c40.193,33.97) 41.369,33.208 ; 41.209,43.111 41.209,43.368 ; 41.209,43.111 41.46,42.86 ; 41.209,43.368 41.209,43.876 ; 41.209,43.368 41.717,43.368 ; 41.209,43.876 41.209,44.384 ; 41.209,43.876 pad.@41.717,43.876 ; 41.209,44.384 41.209,44.892 ; 41.209,44.384 pad.@41.717,44.384 ; 41.209,44.892 41.209,45.4 ; 41.209,44.892 41.717,44.892 ; 41.209,45.4 41.717,45.4 ; 41.209,45.4 41.209,45.625 ; 41.209,45.625 ccw(c41.376,46.714) 41.717,45.667 ; 41.209,53.798 cw(c40.32,53.147) 41.354,53.528 ; 41.209,53.798 41.209,54.036 ; 41.209,54.036 41.209,54.544 ; 41.209,54.036 41.634,54.036 ; 41.209,54.544 41.631,54.544 ; 41.354,53.528 cw(c40.32,53.147) 41.355,53.524 cw(c40.32,53.147) 41.422,53.147 41.422,53.02 ; 41.354,53.528 41.717,53.528 ; 41.369,33.208 41.717,33.208 ; 41.422,48.448 41.717,48.448 ; 41.422,48.448 41.422,48.956 ; 41.422,48.448 41.422,48.227 41.708,47.94 ; 41.422,48.956 41.717,48.956 ; 41.422,48.956 41.422,49.464 ; 41.422,49.464 41.717,49.464 ; 41.422,49.464 41.422,49.972 ; 41.422,49.972 41.422,50.48 ; 41.422,49.972 41.717,49.972 ; 41.422,50.48 41.422,50.988 ; 41.422,50.48 41.717,50.48 ; 41.422,50.988 41.422,51.496 ; 41.422,50.988 41.717,50.988 ; 41.422,51.496 41.422,52.004 ; 41.422,51.496 41.717,51.496 ; 41.422,52.004 41.422,52.512 ; 41.422,52.004 41.717,52.004 ; 41.422,52.512 41.422,53.02 ; 41.422,52.512 41.717,52.512 ; 41.422,53.02 41.717,53.02 ; 41.46,42.86 41.717,42.86 ; 41.46,42.86 41.747,42.573 42.225,42.573 ; 41.499,31.176 cw(c40.193,30.668) 41.502,31.17 cw(c40.193,30.668) 41.595,30.668 ; 41.499,31.176 41.717,31.176 ; 41.595,30.668 41.717,30.668 ; 41.631,54.109 ccw(c42.733,54.109) 41.634,54.036 ; 41.631,54.109 ccw(c42.733,54.109) 41.634,54.036 ; 41.631,54.109 41.631,54.544 ; 41.634,54.036 ccw(c42.733,54.109) 41.717,53.683 ; 41.634,54.036 ccw(c42.733,54.109) 41.717,53.683 ; 41.708,47.94 41.717,47.94 ; 41.708,47.94 41.717,47.931 ; 41.717,20.889 41.717,21.016 ; 41.717,20.889 42.225,20.889 ; 41.717,21.016 41.717,21.524 ; 41.717,21.016 42.225,21.016 ; 41.717,21.524 41.717,22.032 ; 41.717,21.524 42.225,21.524 ; 41.717,22.032 41.717,22.54 ; 41.717,22.032 42.225,22.032 ; 41.717,22.54 41.717,23.048 ; 41.717,22.54 42.225,22.54 ; 41.717,23.048 41.717,23.093 ; 41.717,23.048 42.225,23.048 ; 41.717,23.093 42.225,23.093 ; 41.717,25.797 41.717,26.096 ; 41.717,25.797 42.225,25.797 ; 41.717,26.096 41.717,26.604 ; 41.717,26.096 42.225,26.096 ; 41.717,26.604 42.225,26.604 ; 41.717,26.604 41.717,27.112 ; 41.717,27.112 41.717,27.62 ; 41.717,27.112 42.225,27.112 ; 41.717,27.62 41.717,28.128 ; 41.717,27.62 42.225,27.62 ; 41.717,28.128 41.717,28.636 ; 41.717,28.128 42.225,28.128 ; 41.717,28.636 41.717,29.144 ; 41.717,28.636 42.225,28.636 ; 41.717,29.144 41.717,29.652 ; 41.717,29.144 42.225,29.144 ; 41.717,29.652 41.717,30.16 ; 41.717,29.652 42.225,29.652 ; 41.717,30.16 41.717,30.668 ; 41.717,30.16 42.225,30.16 ; 41.717,30.668 42.225,30.668 ; 41.717,30.668 41.717,31.176 ; 41.717,31.176 41.717,31.684 ; 41.717,31.176 42.225,31.176 ; 41.717,31.684 41.717,32.192 ; 41.717,31.684 42.225,31.684 ; 41.717,32.192 41.717,32.7 ; 41.717,32.192 42.225,32.192 ; 41.717,32.7 41.717,33.208 ; 41.717,32.7 42.225,32.7 ; 41.717,33.208 42.225,33.208 ; 41.717,33.208 41.717,33.604 ; 41.717,33.604 ccw(c42.307,34.389) 42.222,33.41 ccw(c42.307,34.389) 42.225,33.41 ; 41.717,42.86 41.717,43.368 ; 41.717,42.86 42.225,42.86 ; 41.717,43.368 pad.@41.717,43.876 ; 41.717,43.368 42.225,43.368 ; pad.@41.717,43.876 pad.@41.717,44.384 ; pad.@41.717,43.876 pad.@42.225,43.876 ; pad.@41.717,44.384 41.717,44.892 ; pad.@41.717,44.384 pad.@42.225,44.384 ; 41.717,44.892 41.717,45.4 ; 41.717,44.892 42.225,44.892 ; 41.717,45.4 42.225,45.4 ; 41.717,45.4 41.717,45.667 ; 41.717,45.667 ccw(c41.376,46.714) 42.127,45.908 ; 41.717,47.931 41.717,47.94 ; 41.717,47.931 42.155,47.493 cw(c41.376,46.714) 42.212,47.432 ; 41.717,47.94 41.717,48.448 ; 41.717,47.94 42.225,47.94 ; 41.717,48.448 41.717,48.956 ; 41.717,48.448 42.225,48.448 ; 41.717,48.956 41.717,49.464 ; 41.717,48.956 42.225,48.956 ; 41.717,49.464 41.717,49.972 ; 41.717,49.464 42.225,49.464 ; 41.717,49.972 41.717,50.48 ; 41.717,49.972 42.225,49.972 ; 41.717,50.48 42.225,50.48 ; 41.717,50.48 41.717,50.988 ; 41.717,50.988 42.225,50.988 ; 41.717,50.988 41.717,51.496 ; 41.717,51.496 41.717,52.004 ; 41.717,51.496 42.225,51.496 ; 41.717,52.004 42.225,52.004 ; 41.717,52.004 41.717,52.512 ; 41.717,52.512 41.717,53.02 ; 41.717,52.512 42.225,52.512 ; 41.717,53.02 41.717,53.528 ; 41.717,53.02 42.225,53.02 ; 41.717,53.528 41.797,53.528 ; 41.717,53.528 41.717,53.683 ; 41.717,53.683 ccw(c42.733,54.109) 41.719,53.678 ; 41.717,53.683 ccw(c42.733,54.109) 41.719,53.678 ; 41.719,53.678 ccw(c42.733,54.109) 41.797,53.528 ; 41.719,53.678 ccw(c42.733,54.109) 41.797,53.528 ; 41.797,53.528 ccw(c42.733,54.109) 41.954,53.33 cw(c42.733,54.109) 41.797,53.528 ; 42.127,45.908 ccw(c41.376,46.714) 42.22,46.006 ccw(c41.376,46.714) 42.225,46.012 ; 42.127,45.908 42.225,45.908 ; 42.212,47.432 cw(c41.376,46.714) 42.225,47.416 ; 42.212,47.432 42.225,47.432 ; 42.225,20.889 42.225,21.016 ; 42.225,20.889 42.733,20.889 ; 42.225,21.016 42.225,21.524 ; 42.225,21.016 42.733,21.016 ; 42.225,21.524 42.225,22.032 ; 42.225,21.524 42.733,21.524 ; 42.225,22.032 42.225,22.54 ; 42.225,22.032 42.733,22.032 ; 42.225,22.54 42.225,23.048 ; 42.225,22.54 42.733,22.54 ; 42.225,23.048 42.225,23.093 ; 42.225,23.048 42.733,23.048 ; 42.225,23.093 42.733,23.093 ; 42.225,25.797 42.225,26.096 ; 42.225,25.797 42.733,25.797 ; 42.225,26.096 42.225,26.604 ; 42.225,26.096 42.733,26.096 ; 42.225,26.604 42.225,27.112 ; 42.225,26.604 42.733,26.604 ; 42.225,27.112 42.225,27.62 ; 42.225,27.112 42.733,27.112 ; 42.225,27.62 42.225,28.128 ; 42.225,27.62 42.733,27.62 ; 42.225,28.128 42.225,28.636 ; 42.225,28.128 42.733,28.128 ; 42.225,28.636 42.225,29.144 ; 42.225,28.636 42.733,28.636 ; 42.225,29.144 42.225,29.652 ; 42.225,29.144 42.733,29.144 ; 42.225,29.652 42.225,30.16 ; 42.225,29.652 42.733,29.652 ; 42.225,30.16 42.225,30.668 ; 42.225,30.16 42.733,30.16 ; 42.225,30.668 42.225,31.176 ; 42.225,30.668 42.733,30.668 ; 42.225,31.176 42.225,31.684 ; 42.225,31.176 42.733,31.176 ; 42.225,31.684 42.225,32.192 ; 42.225,31.684 42.733,31.684 ; 42.225,32.192 42.225,32.7 ; 42.225,32.192 42.733,32.192 ; 42.225,32.7 42.225,33.208 ; 42.225,32.7 42.733,32.7 ; 42.225,33.208 42.733,33.208 ; 42.225,33.208 42.225,33.41 ; 42.225,33.41 ccw(c42.307,34.389) 42.307,33.407 ccw(c42.307,34.389) 42.733,33.504 ; 42.225,42.573 42.225,42.86 ; 42.225,42.573 42.733,42.573 ; 42.225,42.86 42.225,43.368 ; 42.225,42.86 42.733,42.86 ; 42.225,43.368 pad.@42.225,43.876 ; 42.225,43.368 42.733,43.368 ; pad.@42.225,43.876 42.733,43.876 ; pad.@42.225,43.876 pad.@42.225,44.384 ; pad.@42.225,44.384 42.225,44.892 ; pad.@42.225,44.384 42.733,44.384 ; 42.225,44.892 42.225,45.4 ; 42.225,44.892 42.733,44.892 ; 42.225,45.4 42.225,45.908 ; 42.225,45.4 42.733,45.4 ; 42.225,45.908 42.733,45.908 ; 42.225,45.908 42.225,46.012 ; 42.225,46.012 ccw(c41.376,46.714) 42.436,46.416 ; 42.225,47.416 cw(c41.376,46.714) 42.457,46.924 ; 42.225,47.416 42.225,47.432 ; 42.225,47.432 42.225,47.94 ; 42.225,47.432 42.733,47.432 ; 42.225,47.94 42.225,48.448 ; 42.225,47.94 42.733,47.94 ; 42.225,48.448 42.225,48.956 ; 42.225,48.448 42.733,48.448 ; 42.225,48.956 42.225,49.464 ; 42.225,48.956 42.733,48.956 ; 42.225,49.464 42.225,49.972 ; 42.225,49.464 42.733,49.464 ; 42.225,49.972 42.225,50.48 ; 42.225,49.972 42.733,49.972 ; 42.225,50.48 42.225,50.988 ; 42.225,50.48 42.733,50.48 ; 42.225,50.988 42.225,51.496 ; 42.225,50.988 42.733,50.988 ; 42.225,51.496 42.225,52.004 ; 42.225,51.496 42.733,51.496 ; 42.225,52.004 42.225,52.512 ; 42.225,52.004 42.733,52.004 ; 42.225,52.512 42.733,52.512 ; 42.225,52.512 42.225,53.02 ; 42.225,53.02 42.225,53.059 ; 42.225,53.059 42.733,52.551 ; 42.436,46.416 ccw(c41.376,46.714) 42.478,46.714 ccw(c41.376,46.714) 42.457,46.924 ; 42.436,46.416 42.733,46.416 ; 42.457,46.924 42.733,46.924 ; 42.733,20.889 42.733,21.016 ; 42.733,20.889 43.241,20.889 ; 42.733,21.016 42.733,21.524 ; 42.733,21.016 43.241,21.016 ; 42.733,21.524 42.733,22.032 ; 42.733,21.524 43.241,21.524 ; 42.733,22.032 42.733,22.54 ; 42.733,22.032 43.241,22.032 ; 42.733,22.54 42.733,23.048 ; 42.733,22.54 43.241,22.54 ; 42.733,23.048 42.733,23.093 ; 42.733,23.048 43.241,23.048 ; 42.733,23.093 43.241,23.093 ; 42.733,25.797 42.733,26.096 ; 42.733,25.797 43.241,25.797 ; 42.733,26.096 42.733,26.604 ; 42.733,26.096 43.241,26.096 ; 42.733,26.604 43.241,26.604 ; 42.733,26.604 42.733,27.112 ; 42.733,27.112 42.733,27.62 ; 42.733,27.112 43.241,27.112 ; 42.733,27.62 42.733,28.128 ; 42.733,27.62 43.241,27.62 ; 42.733,28.128 42.733,28.636 ; 42.733,28.128 43.241,28.128 ; 42.733,28.636 42.733,29.144 ; 42.733,28.636 43.241,28.636 ; 42.733,29.144 42.733,29.652 ; 42.733,29.144 43.241,29.144 ; 42.733,29.652 42.733,30.16 ; 42.733,29.652 43.241,29.652 ; 42.733,30.16 42.733,30.668 ; 42.733,30.16 43.241,30.16 ; 42.733,30.668 43.241,30.668 ; 42.733,30.668 42.733,31.176 ; 42.733,31.176 42.733,31.684 ; 42.733,31.176 43.241,31.176 ; 42.733,31.684 42.733,32.192 ; 42.733,31.684 43.241,31.684 ; 42.733,32.192 43.241,32.192 ; 42.733,32.192 42.733,32.7 ; 42.733,32.7 42.733,33.208 ; 42.733,32.7 43.241,32.7 ; 42.733,33.208 43.241,33.208 ; 42.733,33.208 42.733,33.504 ; 42.733,33.504 ccw(c42.307,34.389) 42.738,33.506 ccw(c42.307,34.389) 43.023,33.716 ; 42.733,42.573 42.733,42.86 ; 42.733,42.573 43.192,42.573 ; 42.733,42.86 42.733,43.368 ; 42.733,42.86 43.241,42.86 ; 42.733,43.368 42.733,43.876 ; 42.733,43.368 43.241,43.368 ; 42.733,43.876 42.733,44.384 ; 42.733,43.876 43.241,43.876 ; 42.733,44.384 42.733,44.892 ; 42.733,44.384 43.241,44.384 ; 42.733,44.892 42.733,45.4 ; 42.733,44.892 43.241,44.892 ; 42.733,45.4 43.241,45.4 ; 42.733,45.4 42.733,45.908 ; 42.733,45.908 42.733,46.416 ; 42.733,45.908 43.241,45.908 ; 42.733,46.416 43.241,46.416 ; 42.733,46.416 42.733,46.924 ; 42.733,46.924 42.733,47.432 ; 42.733,46.924 43.241,46.924 ; 42.733,47.432 43.241,47.432 ; 42.733,47.432 42.733,47.94 ; 42.733,47.94 42.733,48.448 ; 42.733,47.94 43.241,47.94 ; 42.733,48.448 42.733,48.956 ; 42.733,48.448 43.241,48.448 ; 42.733,48.956 42.733,49.464 ; 42.733,48.956 43.241,48.956 ; 42.733,49.464 42.733,49.972 ; 42.733,49.464 43.241,49.464 ; 42.733,49.972 42.733,50.48 ; 42.733,49.972 43.241,49.972 ; 42.733,50.48 43.241,50.48 ; 42.733,50.48 42.733,50.988 ; 42.733,50.988 43.241,50.988 ; 42.733,50.988 42.733,51.496 ; 42.733,51.496 42.733,52.004 ; 42.733,51.496 43.15,51.496 ; 42.733,52.004 42.733,52.512 ; 42.733,52.004 43.211,52.004 ; 42.733,52.512 42.772,52.512 ; 42.733,52.512 42.733,52.551 ; 42.733,52.551 42.772,52.512 ; 43.023,33.716 ccw(c42.307,34.389) 43.026,33.719 ccw(c42.307,34.389) 43.241,34.083 ; 43.023,33.716 43.241,33.716 ; 43.15,51.496 cw(c44.575,51.583) 43.211,52.004 ; 43.15,51.496 ccw(c44.575,51.583) 43.241,51.075 ; 43.192,42.573 cw(c43.192,41.844) 43.241,42.571 ; 43.192,42.573 cw(c43.192,41.844) 43.241,42.571 ; 43.228,34.732 cw(c42.307,34.389) 43.241,34.695 ; 43.228,34.732 43.241,34.732 ; 43.241,20.889 43.241,21.016 ; 43.241,20.889 43.749,20.889 ; 43.241,21.016 43.241,21.524 ; 43.241,21.016 43.749,21.016 ; 43.241,21.524 43.241,22.032 ; 43.241,21.524 43.749,21.524 ; 43.241,22.032 43.241,22.54 ; 43.241,22.032 43.749,22.032 ; 43.241,22.54 43.241,23.048 ; 43.241,22.54 43.749,22.54 ; 43.241,23.048 43.241,23.093 ; 43.241,23.048 43.749,23.048 ; 43.241,23.093 43.577,23.093 43.577,23.556 ; 43.241,25.797 43.241,26.096 ; 43.241,25.797 43.577,25.797 43.577,25.588 ; 43.241,26.096 43.241,26.604 ; 43.241,26.096 43.749,26.096 ; 43.241,26.604 43.749,26.604 ; 43.241,26.604 43.241,27.112 ; 43.241,27.112 43.241,27.62 ; 43.241,27.112 43.749,27.112 ; 43.241,27.62 43.241,28.128 ; 43.241,27.62 43.749,27.62 ; 43.241,28.128 43.241,28.636 ; 43.241,28.128 43.749,28.128 ; 43.241,28.636 43.241,29.144 ; 43.241,28.636 pad.@43.749,28.636 ; 43.241,29.144 43.241,29.652 ; 43.241,29.144 43.749,29.144 ; 43.241,29.652 43.241,30.16 ; 43.241,29.652 43.749,29.652 ; 43.241,30.16 43.241,30.668 ; 43.241,30.16 43.749,30.16 ; 43.241,30.668 43.241,31.176 ; 43.241,30.668 43.749,30.668 ; 43.241,31.176 43.241,31.684 ; 43.241,31.176 43.749,31.176 ; 43.241,31.684 43.241,32.192 ; 43.241,31.684 43.749,31.684 ; 43.241,32.192 43.749,32.192 ; 43.241,32.192 43.241,32.7 ; 43.241,32.7 43.241,33.208 ; 43.241,32.7 43.749,32.7 ; 43.241,33.208 43.241,33.716 ; 43.241,33.208 43.749,33.208 ; 43.241,33.716 43.749,33.716 ; 43.241,33.716 43.241,34.083 ; 43.241,34.083 ccw(c42.307,34.389) 43.276,34.224 ; 43.241,34.695 cw(c42.307,34.389) 43.29,34.389 cw(c42.307,34.389) 43.276,34.224 ; 43.241,34.695 43.241,34.732 ; 43.241,34.732 43.241,34.866 ; 43.241,34.732 43.749,34.732 ; 43.241,34.866 43.749,34.866 ; 43.241,42.571 cw(c43.192,41.844) 43.708,42.359 ; 43.241,42.571 cw(c43.192,41.844) 43.708,42.359 ; 43.241,42.571 43.241,42.86 ; 43.241,42.86 43.241,43.368 ; 43.241,42.86 43.749,42.86 ; 43.241,43.368 43.241,43.876 ; 43.241,43.368 43.749,43.368 ; 43.241,43.876 43.241,44.384 ; 43.241,43.876 43.749,43.876 ; 43.241,44.384 43.241,44.892 ; 43.241,44.384 43.749,44.384 ; 43.241,44.892 43.241,45.4 ; 43.241,44.892 43.749,44.892 ; 43.241,45.4 43.749,45.4 ; 43.241,45.4 43.241,45.908 ; 43.241,45.908 43.241,46.416 ; 43.241,45.908 43.749,45.908 ; 43.241,46.416 43.241,46.924 ; 43.241,46.416 43.749,46.416 ; 43.241,46.924 43.241,47.432 ; 43.241,46.924 43.749,46.924 ; 43.241,47.432 43.749,47.432 ; 43.241,47.432 43.241,47.94 ; 43.241,47.94 43.241,48.448 ; 43.241,47.94 43.749,47.94 ; 43.241,48.448 43.241,48.956 ; 43.241,48.448 43.749,48.448 ; 43.241,48.956 43.241,49.464 ; 43.241,48.956 43.749,48.956 ; 43.241,49.464 43.241,49.972 ; 43.241,49.464 43.749,49.464 ; 43.241,49.972 43.241,50.48 ; 43.241,49.972 43.749,49.972 ; 43.241,50.48 43.241,50.988 ; 43.241,50.48 43.669,50.48 ; 43.241,50.988 43.277,50.988 ; 43.241,50.988 43.241,51.075 ; 43.241,51.075 ccw(c44.575,51.583) 43.277,50.988 ; 43.276,34.224 43.749,34.224 ; 43.277,50.988 ccw(c44.575,51.583) 43.669,50.48 ; 43.577,23.556 43.749,23.556 ; 43.577,23.556 43.577,24.064 ; 43.577,24.064 43.749,24.064 ; 43.577,24.064 43.577,24.572 ; 43.577,24.572 43.749,24.572 ; 43.577,24.572 43.577,25.08 ; 43.577,25.08 43.749,25.08 ; 43.577,25.08 43.577,25.588 ; 43.577,25.588 43.749,25.588 ; 43.669,50.48 ccw(c44.575,51.583) 43.749,50.419 ; 43.749,20.889 43.749,21.016 ; 43.749,20.889 44.257,20.889 ; 43.749,21.016 43.749,21.524 ; 43.749,21.016 44.257,21.016 ; 43.749,21.524 43.749,22.032 ; 43.749,21.524 44.257,21.524 ; 43.749,22.032 43.749,22.54 ; 43.749,22.032 44.257,22.032 ; 43.749,22.54 43.749,23.048 ; 43.749,22.54 44.257,22.54 ; 43.749,23.048 43.749,23.556 ; 43.749,23.048 44.257,23.048 ; 43.749,23.556 43.749,24.064 ; 43.749,23.556 44.257,23.556 ; 43.749,24.064 43.749,24.572 ; 43.749,24.064 44.257,24.064 ; 43.749,24.572 43.749,25.08 ; 43.749,24.572 44.257,24.572 ; 43.749,25.08 43.749,25.588 ; 43.749,25.08 44.257,25.08 ; 43.749,25.588 43.749,26.096 ; 43.749,25.588 44.257,25.588 ; 43.749,26.096 43.749,26.604 ; 43.749,26.096 44.257,26.096 ; 43.749,26.604 43.749,27.112 ; 43.749,26.604 44.257,26.604 ; 43.749,27.112 43.749,27.62 ; 43.749,27.112 44.257,27.112 ; 43.749,27.62 43.749,28.128 ; 43.749,27.62 44.257,27.62 ; 43.749,28.128 pad.@43.749,28.636 ; 43.749,28.128 44.257,28.128 ; pad.@43.749,28.636 44.257,28.636 ; pad.@43.749,28.636 43.749,29.144 ; 43.749,29.144 43.749,29.652 ; 43.749,29.144 44.257,29.144 ; 43.749,29.652 43.749,30.16 ; 43.749,29.652 44.257,29.652 ; 43.749,30.16 43.749,30.668 ; 43.749,30.16 44.257,30.16 ; 43.749,30.668 43.749,31.176 ; 43.749,30.668 44.257,30.668 ; 43.749,31.176 43.749,31.684 ; 43.749,31.176 44.257,31.176 ; 43.749,31.684 43.749,32.192 ; 43.749,31.684 44.257,31.684 ; 43.749,32.192 43.749,32.7 ; 43.749,32.192 44.257,32.192 ; 43.749,32.7 43.749,33.208 ; 43.749,32.7 44.257,32.7 ; 43.749,33.208 43.749,33.716 ; 43.749,33.208 44.257,33.208 ; 43.749,33.716 43.749,34.224 ; 43.749,33.716 44.257,33.716 ; 43.749,34.224 43.749,34.732 ; 43.749,34.224 44.257,34.224 ; 43.749,34.732 43.749,34.866 ; 43.749,34.732 44.257,34.732 ; 43.749,34.866 44.257,34.866 ; 43.749,42.352 43.749,42.86 ; 43.749,42.352 43.862,42.352 ; 43.749,42.86 43.749,43.368 ; 43.749,42.86 44.257,42.86 ; 43.749,43.368 43.749,43.876 ; 43.749,43.368 44.257,43.368 ; 43.749,43.876 43.749,44.384 ; 43.749,43.876 44.257,43.876 ; 43.749,44.384 43.749,44.892 ; 43.749,44.384 44.257,44.384 ; 43.749,44.892 43.749,45.4 ; 43.749,44.892 44.257,44.892 ; 43.749,45.4 44.257,45.4 ; 43.749,45.4 43.749,45.908 ; 43.749,45.908 43.749,46.416 ; 43.749,45.908 44.257,45.908 ; 43.749,46.416 43.749,46.924 ; 43.749,46.416 44.257,46.416 ; 43.749,46.924 43.749,47.432 ; 43.749,46.924 44.257,46.924 ; 43.749,47.432 43.749,47.94 ; 43.749,47.432 44.257,47.432 ; 43.749,47.94 43.749,48.448 ; 43.749,47.94 44.257,47.94 ; 43.749,48.448 43.749,48.956 ; 43.749,48.448 EC6.2@44.257,48.448 ; 43.749,48.956 EC6.2@44.257,48.956 ; 43.749,48.956 43.749,49.464 ; 43.749,49.464 43.749,49.972 ; 43.749,49.464 EC6.2@44.257,49.464 ; 43.749,49.972 44.257,49.972 ; 43.749,49.972 43.749,50.419 ; 43.749,50.419 ccw(c44.575,51.583) 44.253,50.192 ccw(c44.575,51.583) 44.257,50.192 ; 43.835,55.052 44.257,55.052 ; 43.835,55.052 43.835,55.56 ; 43.835,55.052 43.835,54.565 43.856,54.544 ; 43.835,55.56 43.835,56.068 ; 43.835,55.56 pad.@44.257,55.56 ; 43.835,56.068 44.257,56.068 ; 43.835,56.068 43.835,56.121 44.765,56.118 ; 43.856,54.544 44.257,54.544 ; 43.856,54.544 44.364,54.036 ; 43.862,42.352 cw(c44.482,41.59) 44.257,42.546 ; 44.257,20.889 44.257,21.016 ; 44.257,20.889 44.765,20.889 ; 44.257,21.016 44.257,21.524 ; 44.257,21.016 44.765,21.016 ; 44.257,21.524 44.257,22.032 ; 44.257,21.524 44.765,21.524 ; 44.257,22.032 44.257,22.54 ; 44.257,22.032 44.765,22.032 ; 44.257,22.54 44.257,23.048 ; 44.257,22.54 44.765,22.54 ; 44.257,23.048 44.257,23.556 ; 44.257,23.048 44.765,23.048 ; 44.257,23.556 44.257,24.064 ; 44.257,23.556 44.765,23.556 ; 44.257,24.064 44.257,24.572 ; 44.257,24.064 44.765,24.064 ; 44.257,24.572 44.257,25.08 ; 44.257,24.572 44.765,24.572 ; 44.257,25.08 44.257,25.588 ; 44.257,25.08 44.765,25.08 ; 44.257,25.588 44.257,26.096 ; 44.257,25.588 44.765,25.588 ; 44.257,26.096 44.257,26.604 ; 44.257,26.096 44.765,26.096 ; 44.257,26.604 44.257,27.112 ; 44.257,26.604 44.765,26.604 ; 44.257,27.112 44.257,27.62 ; 44.257,27.112 44.765,27.112 ; 44.257,27.62 44.257,28.128 ; 44.257,27.62 44.765,27.62 ; 44.257,28.128 44.257,28.636 ; 44.257,28.128 44.765,28.128 ; 44.257,28.636 44.257,29.144 ; 44.257,28.636 44.765,28.636 ; 44.257,29.144 44.257,29.652 ; 44.257,29.144 44.765,29.144 ; 44.257,29.652 44.257,30.16 ; 44.257,29.652 44.765,29.652 ; 44.257,30.16 44.257,30.668 ; 44.257,30.16 44.765,30.16 ; 44.257,30.668 44.257,31.176 ; 44.257,30.668 44.765,30.668 ; 44.257,31.176 44.257,31.684 ; 44.257,31.176 44.765,31.176 ; 44.257,31.684 44.257,32.192 ; 44.257,31.684 44.765,31.684 ; 44.257,32.192 44.257,32.7 ; 44.257,32.192 44.765,32.192 ; 44.257,32.7 44.257,33.208 ; 44.257,32.7 44.765,32.7 ; 44.257,33.208 44.257,33.716 ; 44.257,33.208 44.765,33.208 ; 44.257,33.716 44.257,34.224 ; 44.257,33.716 44.765,33.716 ; 44.257,34.224 44.257,34.732 ; 44.257,34.224 44.765,34.224 ; 44.257,34.732 44.257,34.866 ; 44.257,34.732 44.765,34.732 ; 44.257,34.866 44.765,34.866 ; 44.257,42.546 cw(c44.482,41.59) 44.261,42.547 cw(c44.482,41.59) 44.765,42.531 ; 44.257,42.546 44.257,42.86 ; 44.257,42.86 44.257,43.368 ; 44.257,42.86 44.765,42.86 ; 44.257,43.368 44.257,43.876 ; 44.257,43.368 44.765,43.368 ; 44.257,43.876 44.257,44.384 ; 44.257,43.876 44.765,43.876 ; 44.257,44.384 44.257,44.892 ; 44.257,44.384 44.765,44.384 ; 44.257,44.892 44.257,45.4 ; 44.257,44.892 44.765,44.892 ; 44.257,45.4 44.765,45.4 ; 44.257,45.4 44.257,45.908 ; 44.257,45.908 44.257,46.416 ; 44.257,45.908 44.765,45.908 ; 44.257,46.416 44.765,46.416 ; 44.257,46.416 44.257,46.924 ; 44.257,46.924 44.257,47.432 ; 44.257,46.924 44.765,46.924 ; 44.257,47.432 44.765,47.432 ; 44.257,47.432 44.257,47.94 ; 44.257,47.94 EC6.2@44.257,48.448 ; 44.257,47.94 44.765,47.94 ; EC6.2@44.257,48.448 EC6.2@44.257,48.956 ; EC6.2@44.257,48.448 EC6.2@44.765,48.448 ; EC6.2@44.257,48.956 EC6.2@44.765,48.956 ; EC6.2@44.257,48.956 EC6.2@44.257,49.464 ; EC6.2@44.257,49.464 44.257,49.972 ; EC6.2@44.257,49.464 EC6.2@44.765,49.464 ; 44.257,49.972 44.765,49.972 ; 44.257,49.972 44.257,50.192 ; 44.257,50.192 ccw(c44.575,51.583) 44.575,50.156 44.702,50.156 ccw(c44.702,51.583) 44.765,50.157 ; 44.257,54.544 44.257,55.052 ; 44.257,54.544 44.765,54.544 ; 44.257,55.052 pad.@44.257,55.56 ; 44.257,55.052 44.765,55.052 ; pad.@44.257,55.56 44.765,55.56 ; pad.@44.257,55.56 44.257,56.068 ; 44.257,56.068 44.765,56.068 ; 44.364,54.036 44.872,53.528 ; 44.364,54.036 44.765,54.036 ; 44.765,20.889 44.765,21.016 ; 44.765,20.889 45.273,20.889 ; 44.765,21.016 44.765,21.524 ; 44.765,21.016 45.273,21.016 ; 44.765,21.524 44.765,22.032 ; 44.765,21.524 45.273,21.524 ; 44.765,22.032 44.765,22.54 ; 44.765,22.032 45.273,22.032 ; 44.765,22.54 44.765,23.048 ; 44.765,22.54 45.273,22.54 ; 44.765,23.048 44.765,23.556 ; 44.765,23.048 45.273,23.048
